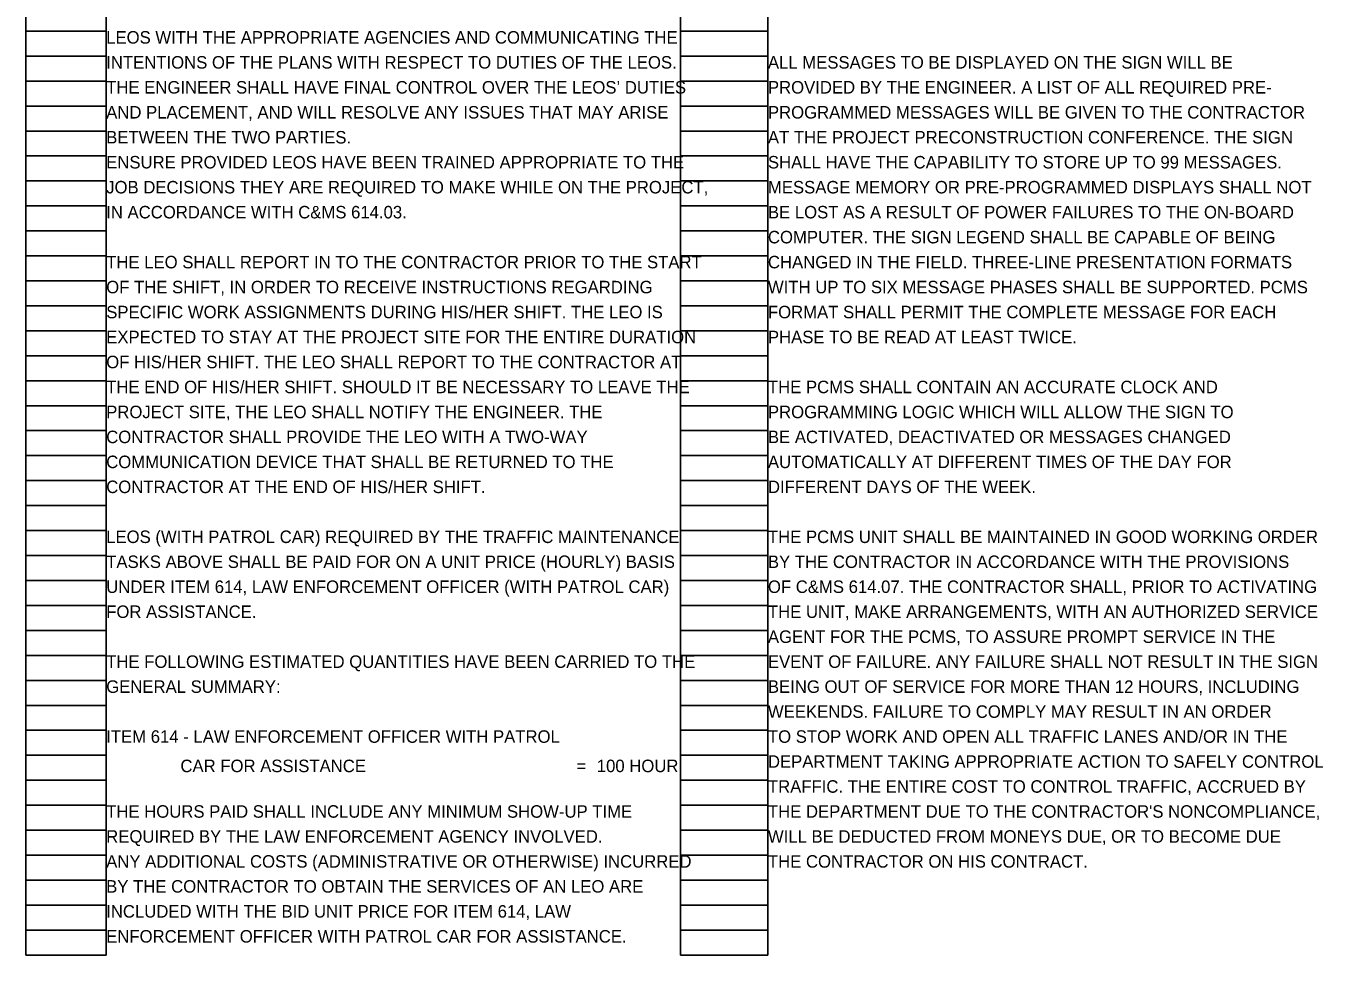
# Model space of a CAD drawing. Extents: x 0 to 32, y -44 to 21.1.
# Drawn here: x 1.5 to 16.04, y -21.02 to -10.6 of the extents above; entities that cross this region are included whole.
import ezdxf

# ---------------------------------------------------------------- set-up
doc = ezdxf.new("R2010")
doc.units = 0
doc.layers.add('SH_Data', color=7, linetype='Continuous')
doc.layers.add('SH_Text', color=7, linetype='Continuous')

msp = doc.modelspace()

# ---------------------------------------------------------------- linework, layer by layer
at = {"layer": 'SH_Data'}
for p, q in [((1.5, -21.02), (1.5, -0.86)), ((2.4, -21.02), (2.4, -0.86)), ((8.84, -21.02), (8.84, -0.86)), ((9.82, -21.02), (9.82, -0.86)), ((1.5, -10.66), (2.4, -10.66)), ((8.84, -10.66), (9.82, -10.66)), ((1.5, -10.94), (2.4, -10.94)), ((8.84, -10.94), (9.82, -10.94)), ((1.5, -11.22), (2.4, -11.22)), ((8.84, -11.22), (9.82, -11.22)), ((1.5, -11.5), (2.4, -11.5)), ((8.84, -11.5), (9.82, -11.5)), ((1.5, -11.78), (2.4, -11.78)), ((8.84, -11.78), (9.82, -11.78)), ((1.5, -12.06), (2.4, -12.06)), ((8.84, -12.06), (9.82, -12.06)), ((1.5, -12.34), (2.4, -12.34)), ((8.84, -12.34), (9.82, -12.34)), ((1.5, -12.62), (2.4, -12.62)), ((8.84, -12.62), (9.82, -12.62)), ((1.5, -12.9), (2.4, -12.9)), ((8.84, -12.9), (9.82, -12.9)), ((1.5, -13.18), (2.4, -13.18)), ((8.84, -13.18), (9.82, -13.18)), ((1.5, -13.46), (2.4, -13.46)), ((8.84, -13.46), (9.82, -13.46)), ((1.5, -13.74), (2.4, -13.74)), ((8.84, -13.74), (9.82, -13.74)), ((1.5, -14.02), (2.4, -14.02)), ((8.84, -14.02), (9.82, -14.02)), ((1.5, -14.3), (2.4, -14.3)), ((8.84, -14.3), (9.82, -14.3)), ((1.5, -14.58), (2.4, -14.58)), ((8.84, -14.58), (9.82, -14.58)), ((1.5, -14.86), (2.4, -14.86)), ((8.84, -14.86), (9.82, -14.86)), ((1.5, -15.14), (2.4, -15.14)), ((8.84, -15.14), (9.82, -15.14)), ((1.5, -15.42), (2.4, -15.42)), ((8.84, -15.42), (9.82, -15.42)), ((1.5, -15.7), (2.4, -15.7)), ((8.84, -15.7), (9.82, -15.7)), ((1.5, -15.98), (2.4, -15.98)), ((8.84, -15.98), (9.82, -15.98)), ((1.5, -16.26), (2.4, -16.26)), ((8.84, -16.26), (9.82, -16.26)), ((1.5, -16.54), (2.4, -16.54)), ((8.84, -16.54), (9.82, -16.54)), ((1.5, -16.82), (2.4, -16.82)), ((8.84, -16.82), (9.82, -16.82)), ((1.5, -17.1), (2.4, -17.1)), ((8.84, -17.1), (9.82, -17.1)), ((1.5, -17.38), (2.4, -17.38)), ((8.84, -17.38), (9.82, -17.38)), ((1.5, -17.66), (2.4, -17.66)), ((8.84, -17.66), (9.82, -17.66)), ((1.5, -17.94), (2.4, -17.94)), ((8.84, -17.94), (9.82, -17.94)), ((1.5, -18.22), (2.4, -18.22)), ((8.84, -18.22), (9.82, -18.22)), ((1.5, -18.5), (2.4, -18.5)), ((8.84, -18.5), (9.82, -18.5)), ((1.5, -18.78), (2.4, -18.78)), ((8.84, -18.78), (9.82, -18.78)), ((1.5, -19.06), (2.4, -19.06)), ((8.84, -19.06), (9.82, -19.06)), ((1.5, -19.34), (2.4, -19.34)), ((8.84, -19.34), (9.82, -19.34)), ((1.5, -19.62), (2.4, -19.62)), ((8.84, -19.62), (9.82, -19.62)), ((1.5, -19.9), (2.4, -19.9)), ((8.84, -19.9), (9.82, -19.9)), ((1.5, -20.18), (2.4, -20.18)), ((8.84, -20.18), (9.82, -20.18)), ((1.5, -20.46), (2.4, -20.46)), ((8.84, -20.46), (9.82, -20.46)), ((1.5, -20.74), (2.4, -20.74)), ((8.84, -20.74), (9.82, -20.74)), ((1.5, -21.02), (2.4, -21.02)), ((8.84, -21.02), (9.82, -21.02))]:
    msp.add_line(p, q, dxfattribs=at)

# ---------------------------------------------------------------- texts
at = {"layer": 'SH_Text'}
for s, p in [('LEOS WITH THE APPROPRIATE AGENCIES AND COMMUNICATING THE ', (2.4, -10.8)), ('INTENTIONS OF THE PLANS WITH RESPECT TO DUTIES OF THE LEOS. ', (2.4, -11.08)), ('ALL MESSAGES TO BE DISPLAYED ON THE SIGN WILL BE', (9.82, -11.08)), ('THE ENGINEER SHALL HAVE FINAL CONTROL OVER THE LEOS’ DUTIES ', (2.4, -11.36)), ('PROVIDED BY THE ENGINEER. A LIST OF ALL REQUIRED PRE-', (9.82, -11.36)), ('AND PLACEMENT, AND WILL RESOLVE ANY ISSUES THAT MAY ARISE ', (2.4, -11.64)), ('PROGRAMMED MESSAGES WILL BE GIVEN TO THE CONTRACTOR', (9.82, -11.64)), ('BETWEEN THE TWO PARTIES. ', (2.4, -11.92)), ('AT THE PROJECT PRECONSTRUCTION CONFERENCE. THE SIGN', (9.82, -11.92)), ('ENSURE PROVIDED LEOS HAVE BEEN TRAINED APPROPRIATE TO THE ', (2.4, -12.2)), ('SHALL HAVE THE CAPABILITY TO STORE UP TO 99 MESSAGES.', (9.82, -12.2)), ('JOB DECISIONS THEY ARE REQUIRED TO MAKE WHILE ON THE PROJECT, ', (2.4, -12.48)), ('MESSAGE MEMORY OR PRE-PROGRAMMED DISPLAYS SHALL NOT', (9.82, -12.48)), ('IN ACCORDANCE WITH C&MS 614.03. ', (2.4, -12.76)), ('BE LOST AS A RESULT OF POWER FAILURES TO THE ON-BOARD', (9.82, -12.76)), ('COMPUTER. THE SIGN LEGEND SHALL BE CAPABLE OF BEING', (9.82, -13.04)), ('THE LEO SHALL REPORT IN TO THE CONTRACTOR PRIOR TO THE START ', (2.4, -13.32)), ('CHANGED IN THE FIELD. THREE-LINE PRESENTATION FORMATS', (9.82, -13.32)), ('OF THE SHIFT, IN ORDER TO RECEIVE INSTRUCTIONS REGARDING ', (2.4, -13.6)), ('WITH UP TO SIX MESSAGE PHASES SHALL BE SUPPORTED. PCMS', (9.82, -13.6)), ('SPECIFIC WORK ASSIGNMENTS DURING HIS/HER SHIFT. THE LEO IS ', (2.4, -13.88)), ('FORMAT SHALL PERMIT THE COMPLETE MESSAGE FOR EACH', (9.82, -13.88)), ('EXPECTED TO STAY AT THE PROJECT SITE FOR THE ENTIRE DURATION ', (2.4, -14.16)), ('PHASE TO BE READ AT LEAST TWICE.', (9.82, -14.16)), ('OF HIS/HER SHIFT. THE LEO SHALL REPORT TO THE CONTRACTOR AT ', (2.4, -14.44)), ('THE END OF HIS/HER SHIFT. SHOULD IT BE NECESSARY TO LEAVE THE ', (2.4, -14.72)), ('THE PCMS SHALL CONTAIN AN ACCURATE CLOCK AND', (9.82, -14.72)), ('PROJECT SITE, THE LEO SHALL NOTIFY THE ENGINEER. THE ', (2.4, -15)), ('PROGRAMMING LOGIC WHICH WILL ALLOW THE SIGN TO', (9.82, -15)), ('CONTRACTOR SHALL PROVIDE THE LEO WITH A TWO-WAY ', (2.4, -15.28)), ('BE ACTIVATED, DEACTIVATED OR MESSAGES CHANGED', (9.82, -15.28)), ('COMMUNICATION DEVICE THAT SHALL BE RETURNED TO THE ', (2.4, -15.56)), ('AUTOMATICALLY AT DIFFERENT TIMES OF THE DAY FOR', (9.82, -15.56)), ('CONTRACTOR AT THE END OF HIS/HER SHIFT.', (2.4, -15.84)), ('DIFFERENT DAYS OF THE WEEK.', (9.82, -15.84)), ('LEOS (WITH PATROL CAR) REQUIRED BY THE TRAFFIC MAINTENANCE ', (2.4, -16.4)), ('THE PCMS UNIT SHALL BE MAINTAINED IN GOOD WORKING ORDER', (9.82, -16.4)), ('TASKS ABOVE SHALL BE PAID FOR ON A UNIT PRICE (HOURLY) BASIS ', (2.4, -16.68)), ('BY THE CONTRACTOR IN ACCORDANCE WITH THE PROVISIONS', (9.82, -16.68)), ('UNDER ITEM 614, LAW ENFORCEMENT OFFICER (WITH PATROL CAR) ', (2.4, -16.96)), ('OF C&MS 614.07. THE CONTRACTOR SHALL, PRIOR TO ACTIVATING', (9.82, -16.96)), ('FOR ASSISTANCE. ', (2.4, -17.24)), ('THE UNIT, MAKE ARRANGEMENTS, WITH AN AUTHORIZED SERVICE', (9.82, -17.24)), ('AGENT FOR THE PCMS, TO ASSURE PROMPT SERVICE IN THE', (9.82, -17.52)), ('THE FOLLOWING ESTIMATED QUANTITIES HAVE BEEN CARRIED TO THE ', (2.4, -17.8)), ('EVENT OF FAILURE. ANY FAILURE SHALL NOT RESULT IN THE SIGN', (9.82, -17.8)), ('GENERAL SUMMARY:', (2.4, -18.08)), ('BEING OUT OF SERVICE FOR MORE THAN 12 HOURS, INCLUDING', (9.82, -18.08)), ('WEEKENDS. FAILURE TO COMPLY MAY RESULT IN AN ORDER', (9.82, -18.36)), ('ITEM 614 - LAW ENFORCEMENT OFFICER WITH PATROL', (2.4, -18.64)), ('TO STOP WORK AND OPEN ALL TRAFFIC LANES AND/OR IN THE', (9.82, -18.64)), ('                CAR FOR ASSISTANCE', (2.4, -18.969)), ('=', (7.672, -18.969)), ('100 HOUR', (7.901, -18.969)), ('DEPARTMENT TAKING APPROPRIATE ACTION TO SAFELY CONTROL', (9.82, -18.92)), ('TRAFFIC. THE ENTIRE COST TO CONTROL TRAFFIC, ACCRUED BY', (9.82, -19.2)), ('THE HOURS PAID SHALL INCLUDE ANY MINIMUM SHOW-UP TIME ', (2.4, -19.48)), ("THE DEPARTMENT DUE TO THE CONTRACTOR'S NONCOMPLIANCE,", (9.82, -19.48)), ('REQUIRED BY THE LAW ENFORCEMENT AGENCY INVOLVED. ', (2.4, -19.76)), ('WILL BE DEDUCTED FROM MONEYS DUE, OR TO BECOME DUE', (9.82, -19.76)), ('ANY ADDITIONAL COSTS (ADMINISTRATIVE OR OTHERWISE) INCURRED ', (2.4, -20.04)), ('THE CONTRACTOR ON HIS CONTRACT.', (9.82, -20.04)), ('BY THE CONTRACTOR TO OBTAIN THE SERVICES OF AN LEO ARE ', (2.4, -20.32)), ('INCLUDED WITH THE BID UNIT PRICE FOR ITEM 614, LAW ', (2.4, -20.6)), ('ENFORCEMENT OFFICER WITH PATROL CAR FOR ASSISTANCE.', (2.4, -20.88))]:
    msp.add_text(s, height=0.14, dxfattribs=at).set_placement(p)

doc.saveas('drawing.dxf')
